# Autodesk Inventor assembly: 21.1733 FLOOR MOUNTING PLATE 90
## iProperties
Created: 2007-04
Part Number: 21.1733 FLOOR MOUNTING PLATE 90
Document SubType Name: Assembly
Designer: Andy Moles
Author: Andy Moles
